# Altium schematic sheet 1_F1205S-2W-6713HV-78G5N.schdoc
size 289 x 200 mm; Name: default297x210; Symbol: default297x210; Device: default297x210; Date: 2026.06.26; Rev: V1.1; Size: "A4"; Id: /; File: F1205S-2W-6713HV-78G5N; Sheet: /; @Page No: 1; @Page Count: 1; @Schematic Name: F1205S-2W-6713HV-78G5N; @Project Name: 全桥隔离电源-F1205S-2W-6713HV-78G5N; @Board Name: F1205S-2W-6713HV-78G5N; @Update Date: 2025-06-26; @Create Time: 14:22:00; @Update Time: 14:24:17; @Page Name: F1205S-2W-6713HV-78G5N; @Create Date: 2025-06-26
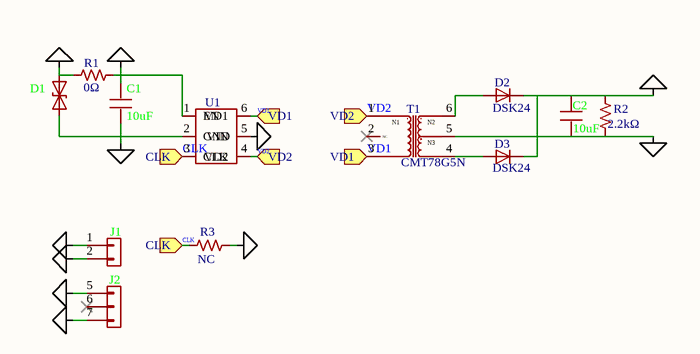
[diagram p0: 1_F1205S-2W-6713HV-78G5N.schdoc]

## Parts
C1  10uF  [C0603]
C2  10uF  [C0603]
D1  (no value)  [SOD-123FL_L2.8-W1.8-LS3.7-BI]
D2  DSK24  [SOD-123_L2.8-W1.8-LS3.7-RD]
D3  DSK24  [SOD-123_L2.8-W1.8-LS3.7-RD]
J1  Connector_Generic_Conn_01x02  [coileasy:PinHeader_01x02_P2.54mm_Vertical]  (value not drawn)
J2  Connector_Generic_Conn_01x03  [coileasy:PinHeader_01x03_1_P2.54mm_Vertical]  (value not drawn)
R1  0Ω  [R0603]
R2  2.2kΩ  [R0603]
R3  NC  [R0603]
T1  CMT78G5N  [SMD-6_L9.7-W8.9-P2.54-LS12.8-TL]
U1  CMP6713HV  [coileasy:SOT-23-6]  (value not drawn)

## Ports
CLK (in), VD1 (in), VD2 (in)

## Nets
0V: C2.1 J2.5 R2.2 T1.5
+VO: C2.2 D2.1 D3.1 J2.7 R2.1
GND: C1.1 D1.2 J1.2 R3.2 U1.2(GND)
VCC: C1.2 R1.2 U1.1(EN) U1.5(VIN)
VIN: D1.1 J1.1 R1.1
CLK: R3.1 U1.3(CLK) ; port CLK
VD1: T1.3 U1.6(VD1) ; port VD1
VD2: T1.1 U1.4(VD2) ; port VD2
NetD2_2: D2.2 T1.6
NetD3_2: D3.2 T1.4

Not connected (* = marked no-connect by the designer): J2 6*; T1 2*

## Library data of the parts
C1 = 0603X106M250NT: Manufacturer: FH(风华); Symbol: My_Library_C; Add into BOM: yes; Tolerance: ±20%; Voltage Rating: 25V; Temperature Coefficient: X5R
C2 = 0603X106K100NT: Manufacturer: FH(风华); Symbol: My_Library_C; Add into BOM: yes; Tolerance: ±10%; Voltage Rated: 10V; Temperature Coefficient: X5R
D1 = SMF28CA_C364280: Symbol: Device_D_TVS; Add into BOM: yes; polarity: 双向; Type: TVS
D2 D3 = DSK24 K24: Manufacturer: MDD(辰达半导体); Symbol: My_Library_D; Add into BOM: yes; Diode Configuration: 独立式; Forward Voltage (Vf@If): 550mV@2A; Reverse Voltage (Vr): 40V; Rectified Current: 2A; Reverse Leakage Current (Ir): 500uA@40V
J1 = Connector_Generic_Conn_01x02: Symbol: Conn_01x04_1; Add into BOM: yes
J2 = Connector_Generic_Conn_01x03: Symbol: Connector_Generic_Conn_01x04; Add into BOM: yes
R1 = RC0603FR-070RL: Manufacturer: YAGEO(国巨); Symbol: My_Library_R; Add into BOM: yes; Tolerance: ±1%; Power(Watts): 100mW; Voltage-Supply(Max): 75V
R2 = RC0603FR-072K2L: Manufacturer: YAGEO(国巨); Symbol: My_Library_R; Add into BOM: yes; Tolerance: ±1%; Power(Watts): 100mW; Voltage-Supply(Max): 75V; Temperature Coefficient: ±100ppm/℃
R3 = RC0603FR-0715KL: Symbol: My_Library_R; Add into BOM: yes; Tolerance: ±1%; Power(Watts): 100mW; Overload Voltage (Max): 75V; Temperature Coefficient: ±100ppm/℃
T1 = CMT78G5N: Manufacturer: coileasy(线易); Symbol: MYLibrary _CMT6870N; Add into BOM: yes
U1 = CMP6713HV: Manufacturer: coileasy(线易); Symbol: Coileasy_SOT23-6; Add into BOM: yes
